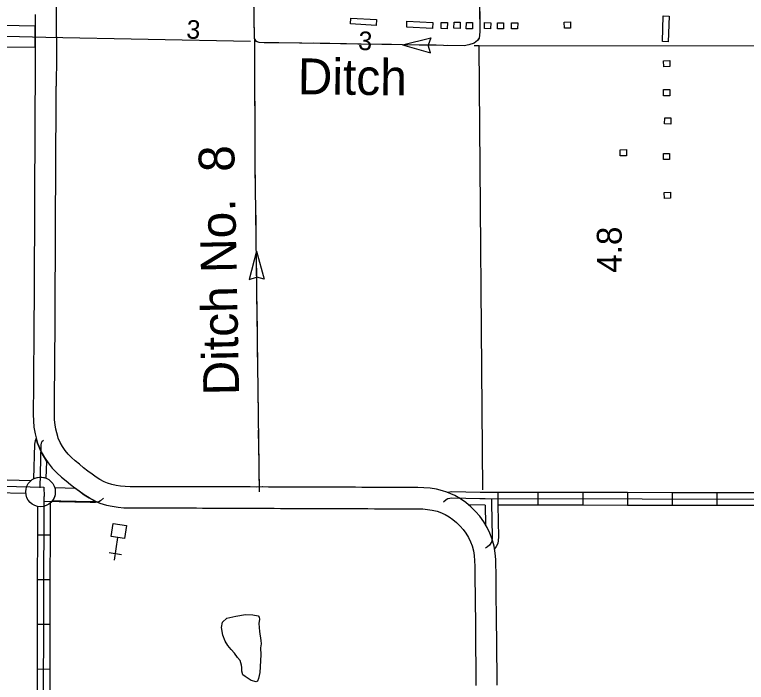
# Model space of a CAD drawing. Extents: x 1366406 to 1373462, y 376856 to 381998.
# Drawn here: x 1369434.3 to 1369574.2, y 379732.3 to 379860 of the extents above; entities that cross this region are included whole.
import ezdxf

# ---------------------------------------------------------------- set-up
doc = ezdxf.new("R2010")
doc.units = 0
for name, color, linetype in [('10', 7, 'Continuous'), ('24', 7, 'Continuous'), ('31', 7, 'Continuous'), ('32', 7, 'Continuous'), ('35', 7, 'Continuous'), ('43', 7, 'Continuous'), ('48', 7, 'Continuous'), ('5', 7, 'Continuous'), ('56', 7, 'Continuous'), ('57', 7, 'Continuous'), ('6', 7, 'Continuous')]:
    doc.layers.add(name, color=color, linetype=linetype)

msp = doc.modelspace()

# ---------------------------------------------------------------- linework, layer by layer
at = {"layer": '10'}
msp.add_line((1369442.29, 379855.73), (1369442.32, 379892.53), dxfattribs=at)
for points in [[(1369438.23, 379859.95), (1369438.24, 379858.8), (1369438.24, 379857.66), (1369438.24, 379856.52), (1369438.24, 379855.74)], [(1369438.23, 379853.74), (1369438.22, 379857.76), (1369432.06, 379857.9)], [(1369438.24, 379856.52), (1369438.18, 379845.11), (1369438.17, 379843.93), (1369438.16, 379842.74), (1369438.16, 379841.54), (1369438.16, 379840.36), (1369438.16, 379839.18), (1369438.15, 379838), (1369438.14, 379836.82), (1369438.14, 379835.63), (1369438.13, 379834.44), (1369438.13, 379833.25), (1369438.12, 379832.06), (1369438.11, 379830.86), (1369438.1, 379829.65), (1369438.1, 379828.45), (1369438.09, 379827.25), (1369438.08, 379826.04), (1369438.07, 379824.83), (1369438.07, 379823.61), (1369438.07, 379822.4), (1369438.06, 379821.18), (1369438.06, 379819.95), (1369438.06, 379818.73), (1369438.05, 379817.5), (1369438.05, 379816.28), (1369438.04, 379815.05), (1369438.03, 379813.82), (1369438.02, 379812.59), (1369438.02, 379811.38), (1369438, 379810.15), (1369438, 379808.92), (1369437.99, 379807.71), (1369437.99, 379806.49), (1369437.99, 379805.27), (1369437.99, 379804.06), (1369437.98, 379802.85), (1369437.97, 379801.64), (1369437.97, 379800.42), (1369437.96, 379799.2), (1369437.95, 379797.97), (1369437.94, 379796.73), (1369437.93, 379795.49), (1369437.92, 379794.26), (1369437.92, 379793.03), (1369437.9, 379791.81), (1369437.89, 379790.58), (1369437.87, 379789.36), (1369437.87, 379788.16), (1369437.86, 379786.98), (1369437.85, 379785.81), (1369437.84, 379784.65), (1369437.85, 379783.5), (1369437.88, 379782.31), (1369437.98, 379781.1), (1369438.18, 379779.86), (1369438.66, 379778.07), (1369438.89, 379777.48), (1369439.37, 379776.39), (1369439.97, 379775.3), (1369440.67, 379774.27), (1369441.46, 379773.28), (1369442.33, 379772.39), (1369443.23, 379771.58), (1369444.12, 379770.85), (1369444.97, 379770.17), (1369445.81, 379769.52), (1369446.67, 379768.85), (1369447.58, 379768.2), (1369448.56, 379767.58), (1369449.57, 379767.06), (1369450.59, 379766.58), (1369451.85, 379766.22), (1369452.94, 379765.98), (1369454.06, 379765.8), (1369455.18, 379765.71), (1369456.25, 379765.68), (1369457.29, 379765.67), (1369458.31, 379765.67), (1369459.33, 379765.66), (1369460.37, 379765.66), (1369461.43, 379765.66), (1369462.48, 379765.67), (1369463.55, 379765.67), (1369464.63, 379765.67), (1369465.72, 379765.67), (1369466.82, 379765.67), (1369467.94, 379765.66), (1369469.07, 379765.66), (1369470.19, 379765.65), (1369471.33, 379765.65), (1369472.47, 379765.64), (1369473.61, 379765.64), (1369474.75, 379765.65), (1369475.88, 379765.65), (1369477.01, 379765.65), (1369478.15, 379765.64), (1369479.29, 379765.63), (1369480.46, 379765.61), (1369481.64, 379765.63)], [(1369442.29, 379855.73), (1369442.29, 379855.39), (1369442.28, 379854.27), (1369442.27, 379853.15), (1369442.27, 379852.02), (1369442.27, 379850.88), (1369442.26, 379849.74), (1369442.25, 379848.58), (1369442.25, 379847.43), (1369442.24, 379846.26)], [(1369432.55, 379853.83), (1369438.23, 379853.74)], [(1369481.59, 379769.68), (1369480.46, 379769.66), (1369479.34, 379769.68), (1369478.18, 379769.69), (1369477.03, 379769.7), (1369475.88, 379769.7), (1369474.73, 379769.7), (1369473.6, 379769.69), (1369472.47, 379769.69), (1369471.35, 379769.7), (1369470.21, 379769.7), (1369469.08, 379769.71), (1369467.96, 379769.71), (1369466.84, 379769.72), (1369465.72, 379769.72), (1369464.63, 379769.72), (1369463.55, 379769.72), (1369462.47, 379769.72), (1369461.41, 379769.71), (1369460.37, 379769.71), (1369459.34, 379769.71), (1369458.31, 379769.72), (1369457.31, 379769.72), (1369456.34, 379769.73), (1369455.41, 379769.76), (1369454.53, 379769.83), (1369453.69, 379769.96), (1369452.84, 379770.15), (1369452.01, 379770.38), (1369451.37, 379770.68), (1369450.58, 379771.09), (1369449.84, 379771.56), (1369449.09, 379772.1), (1369448.3, 379772.71), (1369447.48, 379773.35), (1369446.66, 379774.01), (1369445.87, 379774.65), (1369445.15, 379775.3), (1369444.5, 379775.97), (1369443.93, 379776.68), (1369443.43, 379777.42), (1369443, 379778.19), (1369442.63, 379779.03), (1369442.51, 379779.33), (1369442.14, 379780.71), (1369442, 379781.58), (1369441.92, 379782.53), (1369441.9, 379783.55), (1369441.89, 379784.65), (1369441.9, 379785.78), (1369441.91, 379786.95), (1369441.92, 379788.13), (1369441.92, 379789.33), (1369441.94, 379790.54), (1369441.95, 379791.76), (1369441.97, 379792.99), (1369441.97, 379794.23), (1369441.98, 379795.47), (1369441.99, 379796.71), (1369442, 379797.94), (1369442.01, 379799.17), (1369442.02, 379800.4), (1369442.02, 379801.62), (1369442.03, 379802.83), (1369442.04, 379804.04), (1369442.04, 379805.26), (1369442.04, 379806.48), (1369442.04, 379807.68), (1369442.05, 379808.91), (1369442.05, 379810.13), (1369442.07, 379811.34), (1369442.07, 379812.57), (1369442.08, 379813.8), (1369442.09, 379815.02), (1369442.1, 379816.25), (1369442.1, 379817.49), (1369442.11, 379818.72), (1369442.11, 379819.94), (1369442.11, 379821.16), (1369442.12, 379822.38), (1369442.12, 379823.6), (1369442.12, 379824.81), (1369442.13, 379826.01), (1369442.14, 379827.22), (1369442.15, 379828.43), (1369442.15, 379829.64), (1369442.16, 379830.83), (1369442.17, 379832.03), (1369442.18, 379833.23), (1369442.18, 379834.42), (1369442.19, 379835.61), (1369442.19, 379836.8), (1369442.2, 379837.98), (1369442.21, 379839.17), (1369442.21, 379840.36), (1369442.21, 379841.54), (1369442.21, 379842.71), (1369442.22, 379843.89), (1369442.23, 379845.08), (1369442.24, 379846.26)], [(1369526.53, 379731.77), (1369526.52, 379733.01), (1369526.51, 379734.24), (1369526.5, 379735.48), (1369526.49, 379736.7), (1369526.47, 379737.91), (1369526.46, 379739.12), (1369526.45, 379740.33), (1369526.45, 379741.55), (1369526.43, 379742.76), (1369526.42, 379743.97), (1369526.41, 379745.17), (1369526.39, 379746.37), (1369526.37, 379747.56), (1369526.36, 379748.75), (1369526.35, 379749.93), (1369526.34, 379751.1), (1369526.33, 379752.28), (1369526.32, 379753.45), (1369526.3, 379754.61), (1369526.26, 379755.8), (1369526.17, 379757.05), (1369525.96, 379758.34), (1369525.6, 379759.68), (1369525.15, 379760.82), (1369524.61, 379761.94), (1369523.97, 379763.01), (1369523.23, 379764.08), (1369522.36, 379765.01), (1369521.52, 379765.85), (1369520.56, 379766.69), (1369519.51, 379767.41), (1369518.44, 379768.03), (1369516.93, 379768.7), (1369516.07, 379768.95), (1369514.93, 379769.23), (1369513.73, 379769.42), (1369512.52, 379769.52), (1369511.35, 379769.55), (1369510.2, 379769.56), (1369509.05, 379769.57), (1369507.88, 379769.57), (1369506.7, 379769.57), (1369505.49, 379769.57), (1369504.28, 379769.57), (1369503.08, 379769.58), (1369501.87, 379769.59), (1369500.65, 379769.6), (1369499.43, 379769.62), (1369498.19, 379769.64), (1369496.94, 379769.64), (1369495.72, 379769.64), (1369494.5, 379769.64), (1369493.29, 379769.64), (1369492.09, 379769.64), (1369490.91, 379769.64), (1369489.74, 379769.64), (1369488.57, 379769.64), (1369487.41, 379769.64), (1369486.26, 379769.64), (1369485.1, 379769.64), (1369483.95, 379769.65), (1369482.79, 379769.66), (1369481.64, 379769.68)], [(1369481.6, 379765.63), (1369482.75, 379765.61), (1369483.91, 379765.6), (1369485.08, 379765.59), (1369486.24, 379765.59), (1369487.41, 379765.59), (1369488.58, 379765.59), (1369489.74, 379765.59), (1369490.91, 379765.59), (1369492.09, 379765.59), (1369493.29, 379765.59), (1369494.5, 379765.59), (1369495.72, 379765.59), (1369496.94, 379765.59), (1369498.16, 379765.59), (1369499.37, 379765.57), (1369500.6, 379765.55), (1369501.83, 379765.54), (1369503.05, 379765.53), (1369504.27, 379765.52), (1369505.48, 379765.52), (1369506.68, 379765.52), (1369507.88, 379765.52), (1369509.05, 379765.52), (1369510.18, 379765.51), (1369511.28, 379765.5), (1369512.3, 379765.48), (1369513.24, 379765.4), (1369514.12, 379765.25), (1369515.03, 379765.03), (1369515.54, 379764.89), (1369516.59, 379764.42), (1369517.36, 379763.97), (1369518.08, 379763.48), (1369518.75, 379762.89), (1369519.45, 379762.2), (1369520.06, 379761.54), (1369520.56, 379760.82), (1369521.04, 379760.02), (1369521.44, 379759.18), (1369521.75, 379758.41), (1369521.99, 379757.49), (1369522.14, 379756.58), (1369522.22, 379755.58), (1369522.25, 379754.52), (1369522.27, 379753.39), (1369522.28, 379752.24), (1369522.29, 379751.07), (1369522.3, 379749.89), (1369522.31, 379748.7), (1369522.32, 379747.51), (1369522.34, 379746.31), (1369522.36, 379745.12), (1369522.37, 379743.92), (1369522.38, 379742.72), (1369522.4, 379741.51), (1369522.4, 379740.31), (1369522.41, 379739.09), (1369522.42, 379737.87), (1369522.44, 379736.65), (1369522.45, 379735.43), (1369522.46, 379734.21), (1369522.47, 379732.98), (1369522.48, 379731.74)]]:
    msp.add_lwpolyline(points, dxfattribs=at)
at = {"layer": '24'}
msp.add_circle((1369439.23, 379768.73), 2.83, dxfattribs=at)
at = {"layer": '31'}
for points in [[(1369440.42, 379774.57), (1369439.97, 379775.3), (1369439.37, 379776.39), (1369438.66, 379778.07), (1369438.43, 379778.92), (1369438.2, 379778.49), (1369438.08, 379777.84), (1369437.9, 379771.24), (1369438.19, 379771.38), (1369438.56, 379771.49), (1369439.02, 379771.55), (1369439.49, 379771.56), (1369439.96, 379771.48), (1369440.34, 379771.34)], [(1369439.79, 379778.57), (1369439.49, 379778.33), (1369439.36, 379778.08), (1369439.29, 379777.71), (1369439.07, 379769.51)], [(1369440.34, 379771.34), (1369440.42, 379774.57)], [(1369441.95, 379769.5), (1369442.03, 379769.14), (1369442.06, 379768.71), (1369442.02, 379768.24), (1369441.95, 379767.9), (1369441.79, 379767.5), (1369441.53, 379767.08), (1369443.12, 379767.04)], [(1369449.82, 379766.93), (1369448.56, 379767.58), (1369447.58, 379768.2), (1369445.94, 379769.41), (1369441.95, 379769.5)], [(1369451.24, 379767.51), (1369450.72, 379767.04), (1369450.37, 379766.84), (1369450.09, 379766.79), (1369449.77, 379766.71), (1369449.42, 379766.7), (1369448.75, 379766.7), (1369439.87, 379766.88)], [(1369443.12, 379767.04), (1369448.95, 379766.92), (1369449.82, 379766.93)]]:
    msp.add_lwpolyline(points, dxfattribs=at)
at = {"layer": '32'}
for p, q in [((1369526.68, 379768.64), (1369526.67, 379766.21)), ((1369534.33, 379768.63), (1369534.32, 379766.2)), ((1369542.88, 379768.61), (1369542.88, 379766.18)), ((1369551.44, 379768.59), (1369551.43, 379766.16)), ((1369559.99, 379768.57), (1369559.98, 379766.14)), ((1369568.54, 379768.55), (1369568.54, 379766.12)), ((1369441.13, 379760.48), (1369438.7, 379760.49)), ((1369441.1, 379751.93), (1369438.67, 379751.94)), ((1369441.08, 379743.38), (1369438.65, 379743.38)), ((1369441.06, 379734.82), (1369438.63, 379734.83))]:
    msp.add_line(p, q, dxfattribs=at)
for points in [[(1369396.27, 379770.77), (1369396.96, 379770.76), (1369397.72, 379770.7), (1369400.52, 379770.6), (1369439.87, 379769.64), (1369439.93, 379767.85)], [(1369430.5, 379771.08), (1369437.42, 379770.91)], [(1369430.44, 379768.65), (1369436.4, 379768.51)], [(1369439.06, 379625.24), (1369439.41, 379681.3), (1369439.58, 379691.84), (1369439.82, 379726.65), (1369439.93, 379767.85)], [(1369525.77, 379768.64), (1369524.23, 379768.65), (1369523.26, 379768.65), (1369517.78, 379768.77), (1369517.08, 379768.64)], [(1369534.33, 379768.63), (1369525.77, 379768.64)], [(1369542.88, 379768.61), (1369534.33, 379768.63)], [(1369551.44, 379768.59), (1369542.88, 379768.61)], [(1369559.99, 379768.57), (1369551.44, 379768.59)], [(1369568.54, 379768.55), (1369559.99, 379768.57)], [(1369577.1, 379768.54), (1369568.54, 379768.55)], [(1369441.13, 379760.48), (1369441.14, 379766.64)], [(1369584.25, 379767.31), (1369524.22, 379767.43), (1369523.24, 379767.44), (1369517.87, 379767.55), (1369517.11, 379767.41), (1369516.76, 379767.19), (1369516.24, 379766.8)], [(1369525.44, 379767.45), (1369525.45, 379766.6), (1369525.58, 379760.15), (1369525.49, 379759.25), (1369525.08, 379758.58), (1369524.68, 379758.24), (1369524.32, 379758.01)], [(1369438.7, 379760.49), (1369438.71, 379765.94)], [(1369524.24, 379766.2), (1369521.04, 379766.27)], [(1369524.24, 379766.2), (1369524.32, 379762.43)], [(1369526.67, 379766.21), (1369526.79, 379760.1), (1369526.67, 379758.85), (1369526.34, 379758.32)], [(1369534.32, 379766.2), (1369526.67, 379766.21)], [(1369542.88, 379766.18), (1369534.32, 379766.2)], [(1369551.43, 379766.16), (1369542.88, 379766.18)], [(1369559.98, 379766.14), (1369551.43, 379766.16)], [(1369568.54, 379766.12), (1369559.98, 379766.14)], [(1369577.09, 379766.11), (1369568.54, 379766.12)], [(1369438.67, 379751.94), (1369438.7, 379760.49)], [(1369441.1, 379751.93), (1369441.13, 379760.48)], [(1369526.34, 379758.32), (1369526.04, 379757.83)], [(1369438.65, 379743.38), (1369438.67, 379751.94)], [(1369441.08, 379743.38), (1369441.1, 379751.93)], [(1369438.63, 379734.83), (1369438.65, 379743.38)], [(1369441.06, 379734.82), (1369441.08, 379743.38)], [(1369438.61, 379726.28), (1369438.61, 379726.65), (1369438.63, 379734.83)], [(1369441.04, 379726.26), (1369441.04, 379726.64), (1369441.06, 379734.82)]]:
    msp.add_lwpolyline(points, dxfattribs=at)
at = {"layer": '35'}
for points in [[(1369476.87, 379737.1), (1369476.32, 379737.93), (1369475.65, 379738.64), (1369475.06, 379739.36), (1369474.51, 379740.18), (1369474.06, 379741.33), (1369473.85, 379742.81), (1369473.99, 379743.82), (1369474.82, 379744.63), (1369476.57, 379745.01), (1369478.43, 379745.3), (1369479.81, 379745.21), (1369480.85, 379745.04), (1369481.06, 379744.8), (1369481.08, 379744.42), (1369480.95, 379743.57), (1369481.12, 379742.06), (1369481.34, 379740.31), (1369481.42, 379739.67)], [(1369481.42, 379739.67), (1369481.29, 379738.93), (1369481.32, 379737.58), (1369481.19, 379734.21), (1369480.93, 379733.06), (1369480.71, 379732.58), (1369480.44, 379732.45), (1369479.48, 379732.7), (1369478.37, 379733.48), (1369477.93, 379733.77), (1369477.71, 379734.46), (1369477.72, 379735.17), (1369477.64, 379735.63), (1369477.39, 379736.51), (1369476.87, 379737.1)]]:
    msp.add_lwpolyline(points, dxfattribs=at)
at = {"layer": '43'}
for p, q in [((1369508.44, 379854.19), (1369513.83, 379855.55)), ((1369513.83, 379855.55), (1369513.31, 379854.12)), ((1369508.44, 379854.19), (1369513.78, 379852.67)), ((1369513.78, 379852.67), (1369513.31, 379854.12)), ((1369480.5, 379814.74), (1369479.13, 379809.35)), ((1369480.5, 379814.74), (1369482.01, 379809.39)), ((1369479.13, 379809.35), (1369480.55, 379809.76)), ((1369482.01, 379809.39), (1369480.57, 379809.76))]:
    msp.add_line(p, q, dxfattribs=at)
for points in [[(1369481.08, 379768.77), (1369480.28, 379831.83), (1369480.18, 379855.14), (1369480.17, 379855.4), (1369479.82, 379875.34), (1369444.58, 379895.01), (1369443.11, 379895.83), (1369442.34, 379896.31), (1369441.56, 379896.67), (1369441.11, 379896.82), (1369440.39, 379896.91), (1369439.7, 379896.94), (1369439.19, 379896.92), (1369438.47, 379896.88), (1369436.89, 379896.7), (1369435.3, 379896.45)], [(1369522.68, 379894.83), (1369523.24, 379856.69), (1369523.09, 379855.47), (1369522.74, 379854.98), (1369522.15, 379854.5), (1369521.14, 379854.15), (1369520.25, 379854), (1369484.78, 379854.57), (1369483, 379854.56), (1369481.96, 379854.54), (1369481.01, 379854.64), (1369480.54, 379854.82), (1369480.17, 379855.4)], [(1369480.1, 379859.65), (1369479.99, 379866.06)], [(1369523.13, 379863.83), (1369523.22, 379857.42)], [(1369480.19, 379851.09), (1369480.18, 379855.14), (1369480.17, 379855.4), (1369480.14, 379857.51)], [(1369480.67, 379854.77), (1369480.54, 379854.82), (1369480.17, 379855.4)], [(1369489.19, 379854.5), (1369484.78, 379854.57), (1369483, 379854.56), (1369482.78, 379854.55)], [(1369522.98, 379855.32), (1369522.74, 379854.98), (1369522.15, 379854.5), (1369521.14, 379854.15), (1369520.25, 379854), (1369516.99, 379854.06)], [(1369497.74, 379854.37), (1369491.33, 379854.47)], [(1369506.3, 379854.23), (1369499.88, 379854.33)], [(1369511.64, 379854.14), (1369508.44, 379854.19)], [(1369514.85, 379854.09), (1369511.64, 379854.14)], [(1369480.23, 379842.54), (1369480.2, 379848.96)], [(1369480.27, 379833.99), (1369480.24, 379840.4)], [(1369480.36, 379825.43), (1369480.28, 379831.83), (1369480.28, 379831.85)], [(1369480.43, 379820.09), (1369480.39, 379823.3)], [(1369480.47, 379816.88), (1369480.43, 379820.09)], [(1369480.58, 379808.33), (1369480.5, 379814.74)], [(1369480.69, 379799.78), (1369480.61, 379806.19)], [(1369480.8, 379791.22), (1369480.71, 379797.64)], [(1369480.9, 379782.67), (1369480.82, 379789.08)], [(1369481.01, 379774.12), (1369480.93, 379780.53)], [(1369481.07, 379769.68), (1369481.04, 379771.98)]]:
    msp.add_lwpolyline(points, dxfattribs=at)
at = {"layer": '5'}
for points in [[(1369523.08, 379853.97), (1369522.15, 379853.98)], [(1369523.82, 379769.14), (1369523.08, 379853.97)]]:
    msp.add_lwpolyline(points, dxfattribs=at)
at = {"layer": '56'}
for points in [[(1369498.5, 379858.17), (1369498.56, 379859.29), (1369503.47, 379859.03), (1369503.41, 379857.9)], [(1369558.27, 379859.72), (1369559.4, 379859.69), (1369559.24, 379854.77), (1369558.11, 379854.8)], [(1369509.23, 379857.58), (1369509.29, 379858.7), (1369514.2, 379858.44), (1369514.14, 379857.32)], [(1369515.81, 379857.3), (1369515.85, 379858.47), (1369517.02, 379858.44), (1369516.99, 379857.27)], [(1369518.26, 379857.34), (1369518.28, 379858.51), (1369519.46, 379858.49), (1369519.43, 379857.32)], [(1369520.63, 379857.27), (1369520.65, 379858.44), (1369521.82, 379858.42), (1369521.8, 379857.25)], [(1369524.09, 379857.28), (1369524.13, 379858.45), (1369525.3, 379858.41), (1369525.26, 379857.24)], [(1369526.58, 379857.23), (1369526.59, 379858.4), (1369527.77, 379858.39), (1369527.76, 379857.22)], [(1369529.27, 379857.24), (1369529.27, 379858.41), (1369530.45, 379858.41), (1369530.44, 379857.24)], [(1369539.38, 379857.37), (1369539.36, 379858.54), (1369540.54, 379858.55), (1369540.55, 379857.38)], [(1369558.39, 379849.98), (1369558.35, 379851.15), (1369559.52, 379851.19), (1369559.57, 379850.02)], [(1369558.35, 379844.45), (1369558.36, 379845.63), (1369559.53, 379845.62), (1369559.53, 379844.45)], [(1369558.55, 379839.06), (1369558.58, 379840.23), (1369559.75, 379840.2), (1369559.72, 379839.03)], [(1369550.07, 379832.97), (1369550.06, 379834.14), (1369551.23, 379834.16), (1369551.24, 379832.99)], [(1369558.31, 379832.25), (1369558.31, 379833.42), (1369559.48, 379833.42), (1369559.48, 379832.25)], [(1369558.5, 379824.82), (1369558.47, 379825.99), (1369559.64, 379826.02), (1369559.67, 379824.85)]]:
    msp.add_lwpolyline(points, close=True, dxfattribs=at)
at = {"layer": '57'}
for p, q in [((1369453.36, 379755.7), (1369454.01, 379760.02)), ((1369454.74, 379756.72), (1369452.34, 379757.09))]:
    msp.add_line(p, q, dxfattribs=at)
msp.add_lwpolyline([(1369455.69, 379762.32), (1369455.31, 379759.82), (1369452.72, 379760.21), (1369453.09, 379762.71)], close=True, dxfattribs=at)
at = {"layer": '6'}
for points in [[(1369440.27, 379855.57), (1369397.25, 379856.69), (1369364.11, 379857.55)], [(1369479.36, 379854.82), (1369440.27, 379855.57)], [(1369523.08, 379853.97), (1369522.46, 379853.98)], [(1369610.43, 379853.92), (1369523.08, 379853.97)]]:
    msp.add_lwpolyline(points, dxfattribs=at)

# ---------------------------------------------------------------- texts
at = {"layer": '43'}
for s, height, rotation, p in [('Ditch', 6.843, 359.307, (1369488.38, 379844.76)), ('Ditch No.  8', 6.8429, 91.1578, (1369477.22, 379787.25))]:
    msp.add_text(s, height=height, rotation=rotation, dxfattribs=at).set_placement(p)
at = {"layer": '48'}
msp.add_text('4.8', height=4.752, rotation=90.28, dxfattribs=at).set_placement((1369550.37, 379810.62))
at = {"layer": '56'}
for p in [(1369467.03, 379855.42), (1369499.89, 379853.25)]:
    msp.add_text('3', height=3.56, rotation=356.4139, dxfattribs=at).set_placement(p)

doc.saveas('drawing.dxf')
